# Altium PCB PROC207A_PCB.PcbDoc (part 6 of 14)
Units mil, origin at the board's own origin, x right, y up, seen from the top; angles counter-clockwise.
Board outline 4094.49 x 3724.79 mil, 8 copper layers (Top Layer, L2_GND1, L3_SIG1, L4_PWR1, L5_PWR2, L6_SIG2, L7_GND2, Bottom Layer), stack 58.1 mil thick; 584 components, 399 nets, 8440 pads, 5258 vias.
Unrouted connection lines stored in the file: 9.
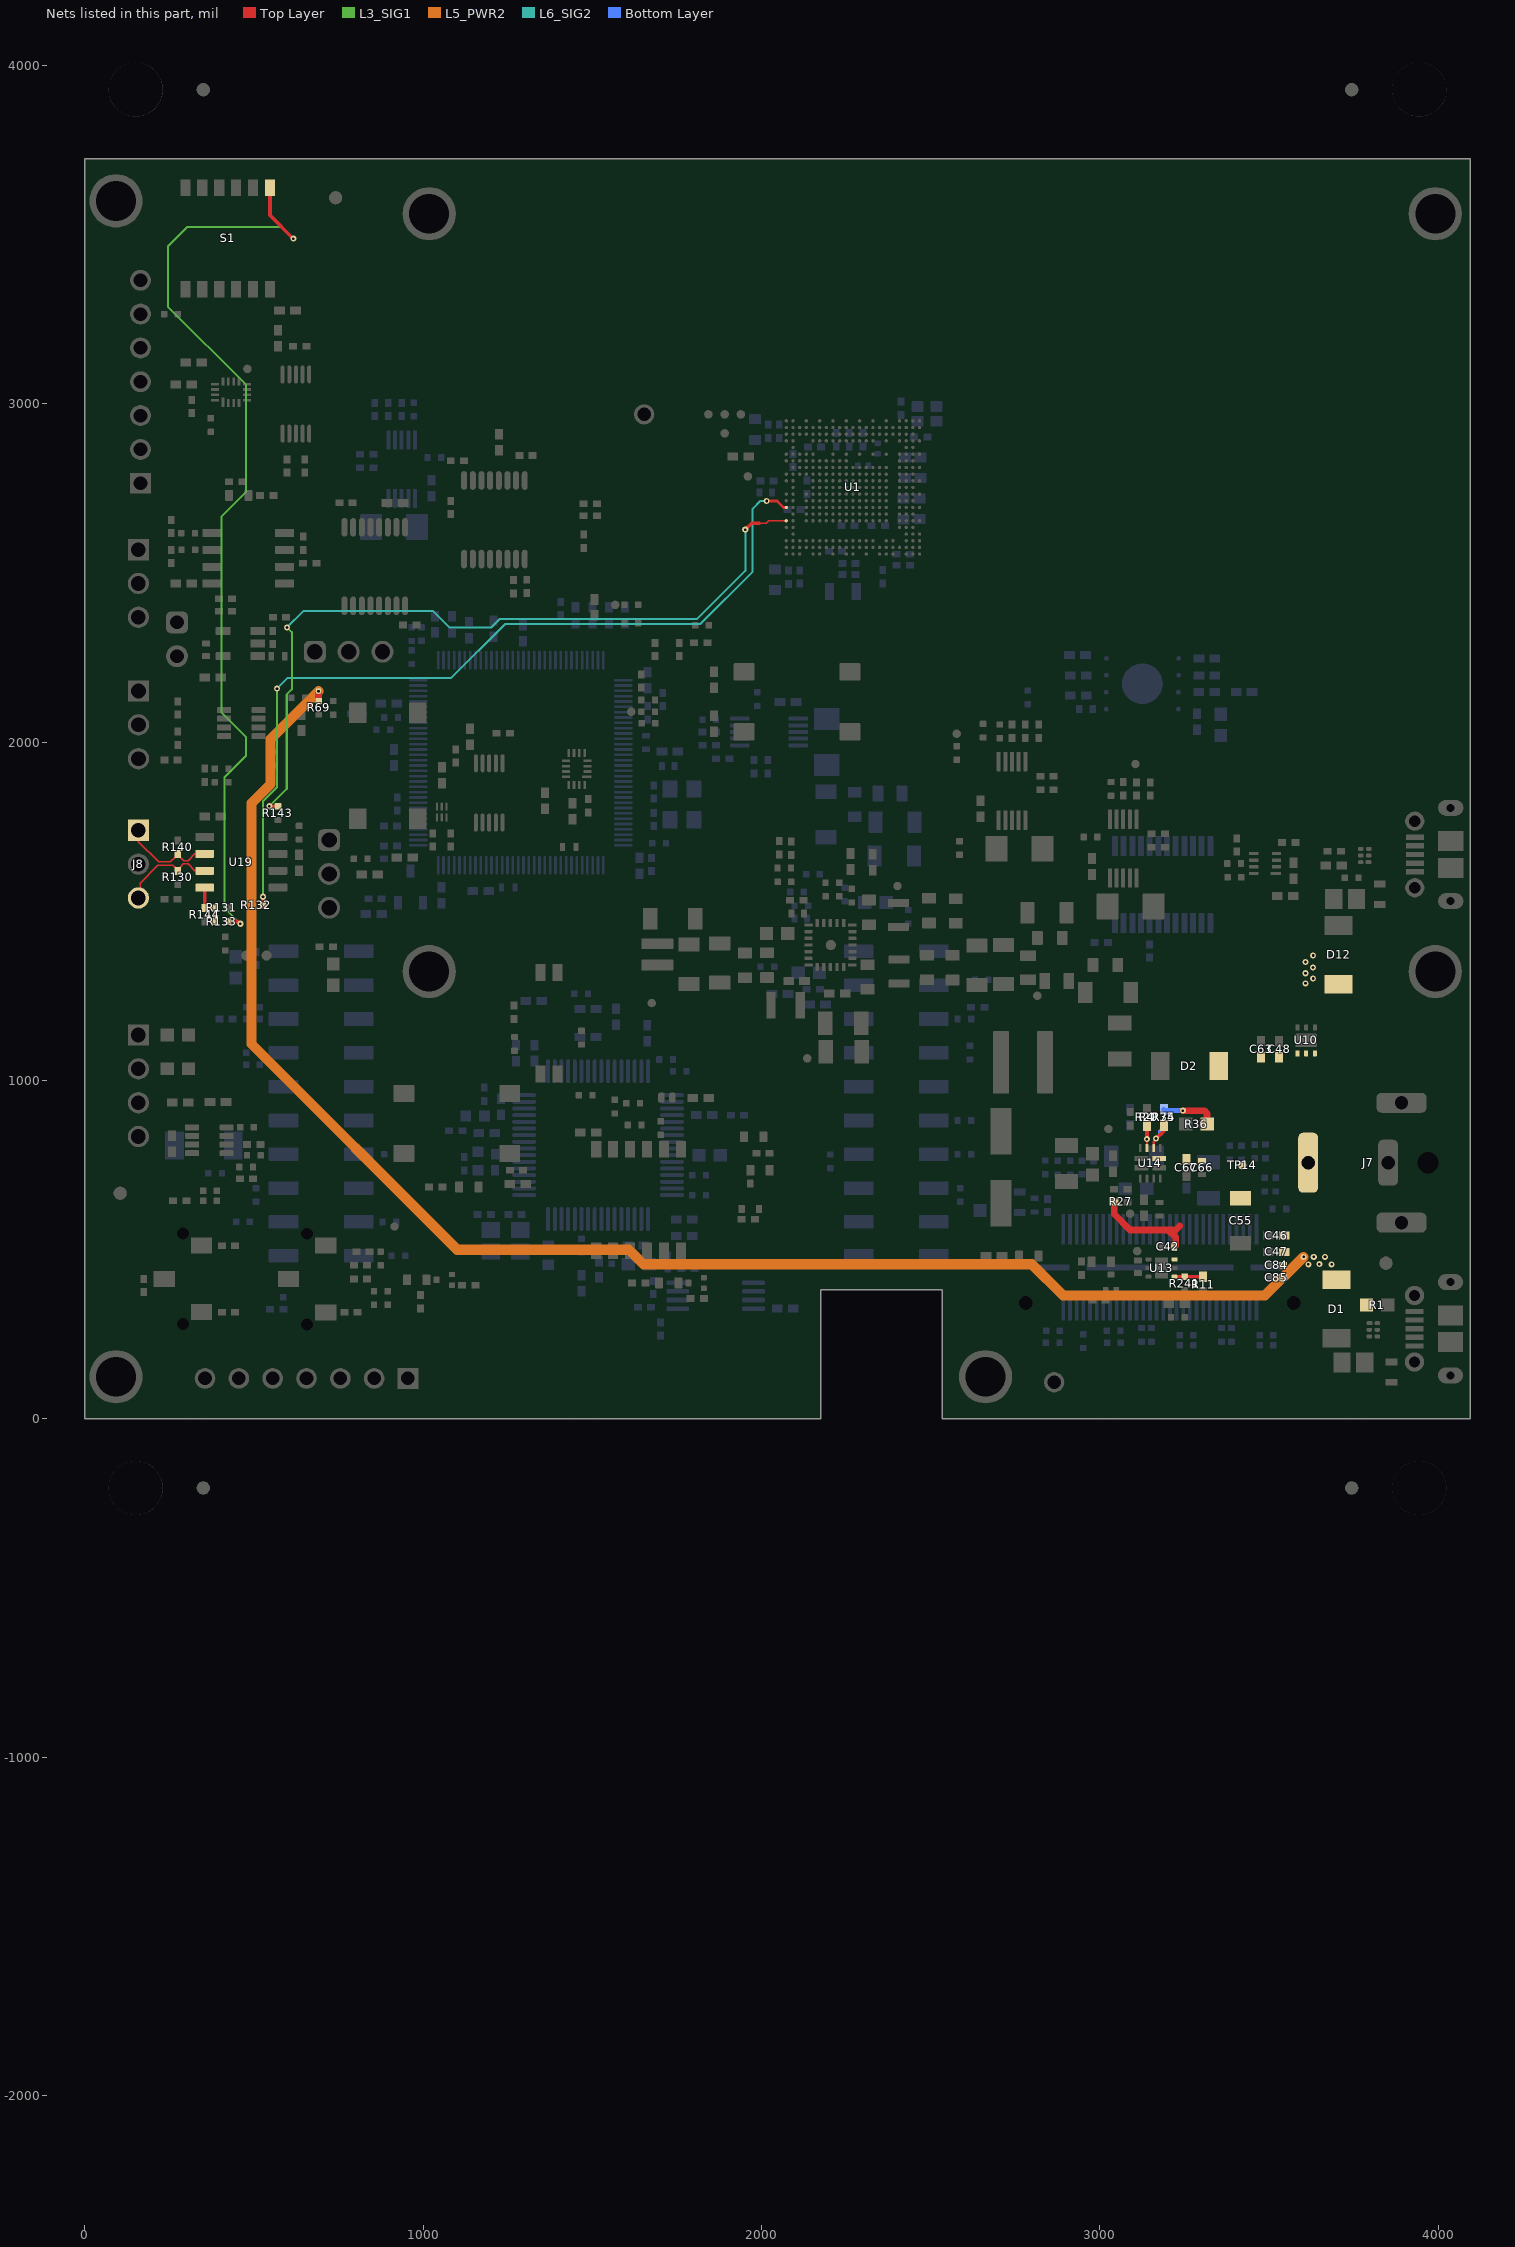
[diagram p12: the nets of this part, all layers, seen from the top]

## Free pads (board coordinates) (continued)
  round 5 on Mech16: 1(1064.44,825) 1(1064.44,825) 1(1064.44,876) 1(1064.44,876) 1(1075.69,801) 1(1075.69,801) 1(1075.69,809.15) 1(1075.69,809.15) 1(1075.69,811.43) 1(1075.69,811.43) 1(1075.69,818.93) 1(1075.69,818.93) 1(1075.69,825) 1(1075.69,825) 1(1084.72,528.51) 1(1084.72,528.51) 1(1084.72,528.53) 1(1084.72,528.53) 1(1084.72,585.53) 1(1084.72,585.53) 1(1084.72,585.55) 1(1084.72,585.55) 1(1087.72,525.53) 1(1087.72,525.53) 1(1087.72,588.53) 1(1087.72,588.53) 1(1093.19,801) 1(1093.19,801) 1(1093.19,809.15) 1(1093.19,809.15) 1(1093.19,811.43) 1(1093.19,811.43) 1(1093.19,818.93) 1(1093.19,818.93) 1(1093.19,825) 1(1093.19,825) 1(1097.34,501.03) 1(1097.34,501.03) 1(1097.34,509.58) 1(1097.34,509.58) 1(1097.34,513.22) 1(1097.34,513.22) 1(1097.34,514.48) 1(1097.34,514.48) 1(1097.34,524.44) 1(1097.34,524.44) 1(1097.34,525.53) 1(1097.34,525.53) 1(1097.34,588.53) 1(1097.34,588.53) 1(1097.34,589.61) 1(1097.34,589.61) 1(1097.34,599.58) 1(1097.34,599.58) 1(1097.34,600.84) 1(1097.34,600.84) 1(1097.34,604.48) 1(1097.34,604.48) 1(1097.34,613.03) 1(1097.34,613.03) 1(1112.1,501.03) 1(1112.1,501.03) 1(1112.1,509.58) 1(1112.1,509.58) 1(1112.1,513.22) 1(1112.1,513.22) 1(1112.1,514.48) 1(1112.1,514.48) 1(1112.1,524.44) 1(1112.1,524.44) 1(1112.1,525.53) 1(1112.1,525.53) 1(1112.1,588.53) 1(1112.1,588.53) 1(1112.1,589.61) 1(1112.1,589.61) 1(1112.1,599.58) 1(1112.1,599.58) 1(1112.1,600.84) 1(1112.1,600.84) 1(1112.1,604.48) 1(1112.1,604.48) 1(1112.1,613.03) 1(1112.1,613.03) 1(1113.19,876) 1(1113.19,876) 1(1113.19,882.06) 1(1113.19,882.06) 1(1113.19,889.56) 1(1113.19,889.56) 1(1113.19,891.84) 1(1113.19,891.84) 1(1113.19,900) 1(1113.19,900) 1(1130.69,876) 1(1130.69,876) 1(1130.69,882.06) 1(1130.69,882.06) 1(1130.69,889.56) 1(1130.69,889.56) 1(1130.69,891.84) 1(1130.69,891.84) 1(1130.69,900) 1(1130.69,900) 1(1134.84,501.03) 1(1134.84,501.03) 1(1134.84,509.58) 1(1134.84,509.58) 1(1134.84,513.22) 1(1134.84,513.22) 1(1134.84,514.48) 1(1134.84,514.48) 1(1134.84,524.44) 1(1134.84,524.44) 1(1134.84,525.53) 1(1134.84,525.53) 1(1134.84,588.53) 1(1134.84,588.53) 1(1134.84,589.61) 1(1134.84,589.61) 1(1134.84,599.58) 1(1134.84,599.58) 1(1134.84,600.84) 1(1134.84,600.84) 1(1134.84,604.48) 1(1134.84,604.48) 1(1134.84,613.03) 1(1134.84,613.03) 1(1149.6,501.03) 1(1149.6,501.03) 1(1149.6,509.58) 1(1149.6,509.58) 1(1149.6,513.22) 1(1149.6,513.22) 1(1149.6,514.48) 1(1149.6,514.48) 1(1149.6,524.44) 1(1149.6,524.44) 1(1149.6,525.53) 1(1149.6,525.53) 1(1149.6,588.53) 1(1149.6,588.53) 1(1149.6,589.61) 1(1149.6,589.61) 1(1149.6,599.58) 1(1149.6,599.58) 1(1149.6,600.84) 1(1149.6,600.84) 1(1149.6,604.48) 1(1149.6,604.48) 1(1149.6,613.03) 1(1149.6,613.03) 1(1150.69,801) 1(1150.69,801) 1(1150.69,809.15) 1(1150.69,809.15) 1(1150.69,811.43) 1(1150.69,811.43) 1(1150.69,818.93) 1(1150.69,818.93) 1(1150.69,825) 1(1150.69,825) 1(1168.19,801) 1(1168.19,801) 1(1168.19,809.15) 1(1168.19,809.15) 1(1168.19,811.43) 1(1168.19,811.43) 1(1168.19,818.93) 1(1168.19,818.93) 1(1168.19,825) 1(1168.19,825) 1(1172.34,501.03) 1(1172.34,501.03) 1(1172.34,509.58) 1(1172.34,509.58) 1(1172.34,513.22) 1(1172.34,513.22) 1(1172.34,514.48) 1(1172.34,514.48) 1(1172.34,524.44) 1(1172.34,524.44) 1(1172.34,525.53) 1(1172.34,525.53) 1(1172.34,588.53) 1(1172.34,588.53) 1(1172.34,589.61) 1(1172.34,589.61) 1(1172.34,599.58) 1(1172.34,599.58) 1(1172.34,600.84) 1(1172.34,600.84) 1(1172.34,604.48) 1(1172.34,604.48) 1(1172.34,613.03) 1(1172.34,613.03) 1(1178.47,534.35) 1(1178.47,534.35) 1(1178.47,544.35) 1(1178.47,544.35) 1(1179.44,825) 1(1179.44,825) 1(1179.44,876) 1(1179.44,876) 1(1187.1,501.03) 1(1187.1,501.03) 1(1187.1,509.58) 1(1187.1,509.58) 1(1187.1,513.22) 1(1187.1,513.22) 1(1187.1,514.48) 1(1187.1,514.48) 1(1187.1,524.44) 1(1187.1,524.44) 1(1187.1,525.53) 1(1187.1,525.53) 1(1187.1,588.53) 1(1187.1,588.53) 1(1187.1,589.61) 1(1187.1,589.61) 1(1187.1,599.58) 1(1187.1,599.58) 1(1187.1,600.84) 1(1187.1,600.84) 1(1187.1,604.48) 1(1187.1,604.48) 1(1187.1,613.03) 1(1187.1,613.03) 1(1196.73,525.53) 1(1196.73,525.53) 1(1196.73,588.53) 1(1196.73,588.53) 1(1199.72,528.51) 1(1199.72,528.51) 1(1199.72,528.53) 1(1199.72,528.53) 1(1199.72,585.53) 1(1199.72,585.53) 1(1199.72,585.55) 1(1199.72,585.55) 1(1305.8,-2261) 1(1305.8,-2261) 1(1305.8,-1761) 1(1305.8,-1761) 1(1896.1,465.3) 1(1896.1,465.3) 1(1896.1,475.15) 1(1896.1,475.15) 1(1896.1,490.89) 1(1896.1,490.89) 1(1896.1,500.74) 1(1896.1,500.74) 1(1896.1,516.48) 1(1896.1,516.48) 1(1896.1,526.33) 1(1896.1,526.33) 1(1896.1,542.07) 1(1896.1,542.07) 1(1896.1,551.92) 1(1896.1,551.92) 1(1907.91,465.3) 1(1907.91,465.3) 1(1907.91,475.15) 1(1907.91,475.15) 1(1907.91,490.89) 1(1907.91,490.89) 1(1907.91,500.74) 1(1907.91,500.74) 1(1907.91,516.48) 1(1907.91,516.48) 1(1907.91,526.33) 1(1907.91,526.33) 1(1907.91,542.07) 1(1907.91,542.07) 1(1907.91,551.92) 1(1907.91,551.92) 1(1913.33,465.3) 1(1913.33,465.3) 1(1913.33,475.15) 1(1913.33,475.15) 1(1913.33,490.89) 1(1913.33,490.89) 1(1913.33,500.74) 1(1913.33,500.74) 1(1913.33,516.48) 1(1913.33,516.48) 1(1913.33,526.33) 1(1913.33,526.33) 1(1913.33,542.07) 1(1913.33,542.07) 1(1913.33,551.92) 1(1913.33,551.92) 1(1918.55,465.3) 1(1918.55,465.3) 1(1918.55,475.15) 1(1918.55,475.15) 1(1918.55,490.89) 1(1918.55,490.89) 1(1918.55,500.74) 1(1918.55,500.74) 1(1918.55,516.48) 1(1918.55,516.48) 1(1918.55,526.33) 1(1918.55,526.33) 1(1918.55,542.07) 1(1918.55,542.07) 1(1918.55,551.92) 1(1918.55,551.92) 1(1927.59,465.3) 1(1927.59,465.3) 1(1927.59,475.15) 1(1927.59,475.15) 1(1927.59,490.89) 1(1927.59,490.89) 1(1927.59,500.74) 1(1927.59,500.74) 1(1927.59,516.48) 1(1927.59,516.48) 1(1927.59,526.33) 1(1927.59,526.33) 1(1927.59,542.07) 1(1927.59,542.07) 1(1927.59,551.92) 1(1927.59,551.92) 1(1933.5,447.39) 1(1933.5,447.39) 1(1933.5,447.39) 1(1933.5,465.3) 1(1933.5,465.3) 1(1933.5,475.15) 1(1933.5,475.15) 1(1933.5,490.89) 1(1933.5,490.89) 1(1933.5,500.74) 1(1933.5,500.74) 1(1933.5,516.48) 1(1933.5,516.48) 1(1933.5,526.33) 1(1933.5,526.33) 1(1933.5,542.07) 1(1933.5,542.07) 1(1933.5,551.92) 1(1933.5,551.92) 1(1933.5,569.44) 1(1933.5,569.44) 1(1933.5,569.44) 1(1937.26,451.16) 1(1937.26,451.16) 1(1937.26,451.16) 1(1937.26,565.67) 1(1937.26,565.67) 1(1937.26,565.67) 1(1952.05,316.38) 1(1952.05,316.38) 1(1952.05,327.06) 1(1952.05,327.06) 1(1952.05,336.06) 1(1952.05,336.06) 1(1952.05,346.74) 1(1952.05,346.74) 1(1952.05,375.42) 1(1952.05,375.42) 1(1952.05,386.1) 1(1952.05,386.1) 1(1952.05,307.38) 1(1952.05,307.38) 1(1952.05,355.74) 1(1952.05,355.74) 1(1952.05,366.42) 1(1952.05,366.42) 1(1952.05,395.1) 1(1952.05,395.1) 1(1953.18,459.2) 1(1953.18,459.2) 1(1953.18,474.95) 1(1953.18,474.95) 1(1961.49,307.38) 1(1961.49,307.38) 1(1961.49,316.38) 1(1961.49,316.38) 1(1961.49,327.06) 1(1961.49,327.06) 1(1961.49,336.06) 1(1961.49,336.06) 1(1961.49,346.74) 1(1961.49,346.74) 1(1961.49,355.74) 1(1961.49,355.74) 1(1961.49,366.42) 1(1961.49,366.42) 1(1961.49,375.42) 1(1961.49,375.42) 1(1961.49,386.1) 1(1961.49,386.1) 1(1961.49,395.1) 1(1961.49,395.1) 1(1966.21,307.38) 1(1966.21,307.38) 1(1966.21,316.38) 1(1966.21,316.38) 1(1966.21,327.06) 1(1966.21,327.06) 1(1966.21,336.06) 1(1966.21,336.06) 1(1966.21,346.74) 1(1966.21,346.74) 1(1966.21,355.74) 1(1966.21,355.74) 1(1966.21,366.42) 1(1966.21,366.42) 1(1966.21,375.42) 1(1966.21,375.42) 1(1966.21,386.1) 1(1966.21,386.1) 1(1966.21,395.1) 1(1966.21,395.1) 1(1966.34,307.38) 1(1966.34,307.38) 1(1966.34,316.38) 1(1966.34,316.38) 1(1966.34,327.06) 1(1966.34,327.06) 1(1966.34,336.06) 1(1966.34,336.06) 1(1966.34,346.74) 1(1966.34,346.74) 1(1966.34,355.74) 1(1966.34,355.74) 1(1966.34,366.42) 1(1966.34,366.42) 1(1966.34,375.42) 1(1966.34,375.42) 1(1966.34,386.1) 1(1966.34,386.1) 1(1966.34,395.1) 1(1966.34,395.1) 1(1978.29,307.38) 1(1978.29,307.38) 1(1978.29,316.38) 1(1978.29,316.38) 1(1978.29,327.06) 1(1978.29,327.06) 1(1978.29,336.06) 1(1978.29,336.06) 1(1978.29,346.74) 1(1978.29,346.74) 1(1978.29,355.74) 1(1978.29,355.74) 1(1978.29,366.42) 1(1978.29,366.42) 1(1978.29,375.42) 1(1978.29,375.42) 1(1978.29,386.1) 1(1978.29,386.1) 1(1978.29,395.1) 1(1978.29,395.1) 1(1989.55,297.24) 1(1989.55,297.24) 1(1989.55,307.38) 1(1989.55,307.38) 1(1989.55,316.38) 1(1989.55,316.38) 1(1989.55,327.06) 1(1989.55,327.06) 1(1989.55,336.06) 1(1989.55,336.06) 1(1989.55,346.74) 1(1989.55,346.74) 1(1989.55,355.74) 1(1989.55,355.74) 1(1989.55,366.42) 1(1989.55,366.42) 1(1989.55,375.42) 1(1989.55,375.42) 1(1989.55,386.1) 1(1989.55,386.1) 1(1989.55,395.1) 1(1989.55,395.1) 1(1989.55,405.24) 1(1989.55,405.24) 1(1989.56,297.14) 1(1989.56,297.14) 1(1989.56,405.35) 1(1989.56,405.35) 1(1990.64,-469.68) 1(1990.64,-469.68) 1(1990.64,-389.68) 1(1990.64,-389.68) 1(1990.64,-73.54) 1(1990.64,-73.54) 1(1990.64,6.46) 1(1990.64,6.46) 1(1994.45,292.24) 1(1994.45,292.24) 1(1994.45,410.24) 1(1994.45,410.24) 1(1994.55,292.24) 1(1994.55,292.24) 1(1994.55,410.24) 1(1994.55,410.24) 1(1996.55,313.24) 1(1996.55,313.24) 1(2010.36,-819.84) 1(2010.36,-819.84) 1(2010.36,-809.16) 1(2010.36,-809.16) 1(2010.36,-800.16) 1(2010.36,-800.16) 1(2010.36,-789.48) 1(2010.36,-789.48) 1(2010.36,-760.8) 1(2010.36,-760.8) 1(2010.36,-750.12) 1(2010.36,-750.12) 1(2010.36,-828.84) 1(2010.36,-828.84) 1(2010.36,-780.48) 1(2010.36,-780.48) 1(2010.36,-769.8) 1(2010.36,-769.8) 1(2010.36,-741.12) 1(2010.36,-741.12) 1(2019.79,-828.84) 1(2019.79,-828.84) 1(2019.79,-819.84) 1(2019.79,-819.84) 1(2019.79,-809.16) 1(2019.79,-809.16) 1(2019.79,-800.16) 1(2019.79,-800.16) 1(2019.79,-789.48) 1(2019.79,-789.48) 1(2019.79,-780.48) 1(2019.79,-780.48) 1(2019.79,-769.8) 1(2019.79,-769.8) 1(2019.79,-760.8) 1(2019.79,-760.8) 1(2019.79,-750.12) 1(2019.79,-750.12) 1(2019.79,-741.12) 1(2019.79,-741.12) 1(2024.51,-828.84) 1(2024.51,-828.84) 1(2024.51,-819.84) 1(2024.51,-819.84) 1(2024.51,-809.16) 1(2024.51,-809.16) 1(2024.51,-800.16) 1(2024.51,-800.16) 1(2024.51,-789.48) 1(2024.51,-789.48) 1(2024.51,-780.48) 1(2024.51,-780.48) 1(2024.51,-769.8) 1(2024.51,-769.8) 1(2024.51,-760.8) 1(2024.51,-760.8) 1(2024.51,-750.12) 1(2024.51,-750.12) 1(2024.51,-741.12) 1(2024.51,-741.12) 1(2024.55,313.24) 1(2024.55,313.24) 1(2024.64,-828.84) 1(2024.64,-828.84) 1(2024.64,-819.84) 1(2024.64,-819.84) 1(2024.64,-809.16) 1(2024.64,-809.16) 1(2024.64,-800.16) 1(2024.64,-800.16) 1(2024.64,-789.48) 1(2024.64,-789.48) 1(2024.64,-780.48) 1(2024.64,-780.48) 1(2024.64,-769.8) 1(2024.64,-769.8) 1(2024.64,-760.8) 1(2024.64,-760.8) 1(2024.64,-750.12) 1(2024.64,-750.12) 1(2024.64,-741.12) 1(2024.64,-741.12) 1(2036.6,-828.84) 1(2036.6,-828.84) 1(2036.6,-819.84) 1(2036.6,-819.84) 1(2036.6,-809.16) 1(2036.6,-809.16) 1(2036.6,-800.16) 1(2036.6,-800.16) 1(2036.6,-789.48) 1(2036.6,-789.48) 1(2036.6,-780.48) 1(2036.6,-780.48) 1(2036.6,-769.8) 1(2036.6,-769.8) 1(2036.6,-760.8) 1(2036.6,-760.8) 1(2036.6,-750.12) 1(2036.6,-750.12) 1(2036.6,-741.12) 1(2036.6,-741.12) 1(2047.86,-838.98) 1(2047.86,-838.98) 1(2047.86,-828.84) 1(2047.86,-828.84) 1(2047.86,-819.84) 1(2047.86,-819.84) 1(2047.86,-809.16) 1(2047.86,-809.16) 1(2047.86,-800.16) 1(2047.86,-800.16) 1(2047.86,-789.48) 1(2047.86,-789.48) 1(2047.86,-780.48) 1(2047.86,-780.48) 1(2047.86,-769.8) 1(2047.86,-769.8) 1(2047.86,-760.8) 1(2047.86,-760.8) 1(2047.86,-750.12) 1(2047.86,-750.12) 1(2047.86,-741.12) 1(2047.86,-741.12) 1(2047.86,-730.98) 1(2047.86,-730.98) 1(2047.86,-839.09) 1(2047.86,-839.09) 1(2047.86,-730.87) 1(2047.86,-730.87) 1(2052.75,-843.98) 1(2052.75,-843.98) 1(2052.75,-725.98) 1(2052.75,-725.98) 1(2052.86,-843.98) 1(2052.86,-843.98) 1(2052.86,-725.98) 1(2052.86,-725.98) 1(2054.86,-822.98) 1(2054.86,-822.98) 1(2082.86,-822.98) 1(2082.86,-822.98) 1(2102.55,292.24) 1(2102.55,292.24) 1(2102.55,410.24) 1(2102.55,410.24) 1(2102.66,292.24) 1(2102.66,292.24) 1(2102.66,410.24) 1(2102.66,410.24) 1(2106.9,451.16) 1(2106.9,451.16) 1(2106.9,451.16) 1(2106.9,565.67) 1(2106.9,565.67) 1(2106.9,565.67) 1(2107.55,297.14) 1(2107.55,297.14) 1(2107.55,405.35) 1(2107.55,405.35) 1(2107.55,297.24) 1(2107.55,297.24) 1(2107.55,307.38) 1(2107.55,307.38) 1(2107.55,316.38) 1(2107.55,316.38) 1(2107.55,327.06) 1(2107.55,327.06) 1(2107.55,336.06) 1(2107.55,336.06) 1(2107.55,346.74) 1(2107.55,346.74) 1(2107.55,355.74) 1(2107.55,355.74) 1(2107.55,366.42) 1(2107.55,366.42) 1(2107.55,375.42) 1(2107.55,375.42) 1(2107.55,386.1) 1(2107.55,386.1) 1(2107.55,395.1) 1(2107.55,395.1) 1(2107.55,405.24) 1(2107.55,405.24) 1(2110.66,447.39) 1(2110.66,447.39) 1(2110.66,447.39) 1(2110.66,465.3) 1(2110.66,465.3) 1(2110.66,475.15) 1(2110.66,475.15) 1(2110.66,490.89) 1(2110.66,490.89) 1(2110.66,500.74) 1(2110.66,500.74) 1(2110.66,516.48) 1(2110.66,516.48) 1(2110.66,526.33) 1(2110.66,526.33) 1(2110.66,542.07) 1(2110.66,542.07) 1(2110.66,551.92) 1(2110.66,551.92) 1(2110.66,569.44) 1(2110.66,569.44) 1(2110.66,569.44) 1(2116.57,465.3) 1(2116.57,465.3) 1(2116.57,475.15) 1(2116.57,475.15) 1(2116.57,490.89) 1(2116.57,490.89) 1(2116.57,500.74) 1(2116.57,500.74) 1(2116.57,516.48) 1(2116.57,516.48) 1(2116.57,526.33) 1(2116.57,526.33) 1(2116.57,542.07) 1(2116.57,542.07) 1(2116.57,551.92) 1(2116.57,551.92) 1(2118.82,307.38) 1(2118.82,307.38) 1(2118.82,316.38) 1(2118.82,316.38) 1(2118.82,327.06) 1(2118.82,327.06) 1(2118.82,336.06) 1(2118.82,336.06) 1(2118.82,346.74) 1(2118.82,346.74) 1(2118.82,355.74) 1(2118.82,355.74) 1(2118.82,366.42) 1(2118.82,366.42) 1(2118.82,395.1) 1(2118.82,395.1) 1(2118.82,375.42) 1(2118.82,375.42) 1(2118.82,386.1) 1(2118.82,386.1) 1(2125.61,465.3) 1(2125.61,465.3) 1(2125.61,475.15) 1(2125.61,475.15) 1(2125.61,490.89) 1(2125.61,490.89) 1(2125.61,500.74) 1(2125.61,500.74) 1(2125.61,516.48) 1(2125.61,516.48) 1(2125.61,526.33) 1(2125.61,526.33) 1(2125.61,542.07) 1(2125.61,542.07) 1(2125.61,551.92) 1(2125.61,551.92) 1(2130.77,307.38) 1(2130.77,307.38) 1(2130.77,316.38) 1(2130.77,316.38) 1(2130.77,327.06) 1(2130.77,327.06) 1(2130.77,336.06) 1(2130.77,336.06) 1(2130.77,346.74) 1(2130.77,346.74) 1(2130.77,355.74) 1(2130.77,355.74) 1(2130.77,366.42) 1(2130.77,366.42) 1(2130.77,375.42) 1(2130.77,375.42) 1(2130.77,386.1) 1(2130.77,386.1) 1(2130.77,395.1) 1(2130.77,395.1) 1(2130.83,465.3) 1(2130.83,465.3) 1(2130.83,475.15) 1(2130.83,475.15) 1(2130.83,490.89) 1(2130.83,490.89) 1(2130.83,500.74) 1(2130.83,500.74) 1(2130.83,516.48) 1(2130.83,516.48) 1(2130.83,526.33) 1(2130.83,526.33) 1(2130.83,542.07) 1(2130.83,542.07) 1(2130.83,551.92) 1(2130.83,551.92) 1(2130.9,375.42) 1(2130.9,375.42) 1(2130.9,386.1) 1(2130.9,386.1) 1(2130.9,307.38) 1(2130.9,307.38) 1(2130.9,316.38) 1(2130.9,316.38) 1(2130.9,327.06) 1(2130.9,327.06) 1(2130.9,336.06) 1(2130.9,336.06) 1(2130.9,346.74) 1(2130.9,346.74) 1(2130.9,355.74) 1(2130.9,355.74) 1(2130.9,366.42) 1(2130.9,366.42) 1(2130.9,395.1) 1(2130.9,395.1) 1(2135.62,307.38) 1(2135.62,307.38) 1(2135.62,316.38) 1(2135.62,316.38) 1(2135.62,327.06) 1(2135.62,327.06) 1(2135.62,336.06) 1(2135.62,336.06) 1(2135.62,346.74) 1(2135.62,346.74) 1(2135.62,355.74) 1(2135.62,355.74) 1(2135.62,366.42) 1(2135.62,366.42) 1(2135.62,375.42) 1(2135.62,375.42) 1(2135.62,386.1) 1(2135.62,386.1) 1(2135.62,395.1) 1(2135.62,395.1) 1(2136.25,465.3) 1(2136.25,465.3) 1(2136.25,475.15) 1(2136.25,475.15) 1(2136.25,490.89) 1(2136.25,490.89) 1(2136.25,500.74) 1(2136.25,500.74) 1(2136.25,516.48) 1(2136.25,516.48) 1(2136.25,526.33) 1(2136.25,526.33) 1(2136.25,542.07) 1(2136.25,542.07) 1(2136.25,551.92) 1(2136.25,551.92) 1(2136.64,-73.54) 1(2136.64,-73.54) 1(2136.64,6.46) 1(2136.64,6.46) 1(2138.64,-469.68) 1(2138.64,-469.68) 1(2138.64,-469.54) 1(2138.64,-469.54) 1(2138.64,-389.68) 1(2138.64,-389.68) 1(2138.64,-389.54) 1(2138.64,-389.54) 1(2138.64,-73.54) 1(2138.64,-73.54) 1(2138.64,6.46) 1(2138.64,6.46) 1(2145.05,307.38) 1(2145.05,307.38) 1(2145.05,316.38) 1(2145.05,316.38) 1(2145.05,327.06) 1(2145.05,327.06) 1(2145.05,336.06) 1(2145.05,336.06) 1(2145.05,346.74) 1(2145.05,346.74) 1(2145.05,355.74) 1(2145.05,355.74) 1(2145.05,366.42) 1(2145.05,366.42) 1(2145.05,375.42) 1(2145.05,375.42) 1(2145.05,386.1) 1(2145.05,386.1) 1(2145.05,395.1) 1(2145.05,395.1) 1(2148.06,465.3) 1(2148.06,465.3) 1(2148.06,475.15) 1(2148.06,475.15) 1(2148.06,490.89) 1(2148.06,490.89) 1(2148.06,500.74) 1(2148.06,500.74) 1(2148.06,516.48) 1(2148.06,516.48) 1(2148.06,526.33) 1(2148.06,526.33) 1(2148.06,542.07) 1(2148.06,542.07) 1(2148.06,551.92) 1(2148.06,551.92) 1(2160.86,-843.98) 1(2160.86,-843.98) 1(2160.86,-725.98) 1(2160.86,-725.98) 1(2160.97,-843.98) 1(2160.97,-843.98) 1(2160.97,-725.98) 1(2160.97,-725.98) 1(2165.86,-839.09) 1(2165.86,-839.09) 1(2165.86,-730.87) 1(2165.86,-730.87) 1(2165.86,-838.98) 1(2165.86,-838.98) 1(2165.86,-828.84) 1(2165.86,-828.84) 1(2165.86,-819.84) 1(2165.86,-819.84) 1(2165.86,-809.16) 1(2165.86,-809.16) 1(2165.86,-800.16) 1(2165.86,-800.16) 1(2165.86,-789.48) 1(2165.86,-789.48) 1(2165.86,-780.48) 1(2165.86,-780.48) 1(2165.86,-769.8) 1(2165.86,-769.8) 1(2165.86,-760.8) 1(2165.86,-760.8) 1(2165.86,-750.12) 1(2165.86,-750.12) 1(2165.86,-741.12) 1(2165.86,-741.12) 1(2165.86,-730.98) 1(2165.86,-730.98) 1(2177.12,-828.84) 1(2177.12,-828.84) 1(2177.12,-819.84) 1(2177.12,-819.84) 1(2177.12,-809.16) 1(2177.12,-809.16) 1(2177.12,-800.16) 1(2177.12,-800.16) 1(2177.12,-789.48) 1(2177.12,-789.48) 1(2177.12,-780.48) 1(2177.12,-780.48) 1(2177.12,-769.8) 1(2177.12,-769.8) 1(2177.12,-741.12) 1(2177.12,-741.12) 1(2177.12,-760.8) 1(2177.12,-760.8) 1(2177.12,-750.12) 1(2177.12,-750.12) 1(2189.08,-828.84) 1(2189.08,-828.84) 1(2189.08,-819.84) 1(2189.08,-819.84) 1(2189.08,-809.16) 1(2189.08,-809.16) 1(2189.08,-800.16) 1(2189.08,-800.16) 1(2189.08,-789.48) 1(2189.08,-789.48) 1(2189.08,-780.48) 1(2189.08,-780.48) 1(2189.08,-769.8) 1(2189.08,-769.8) 1(2189.08,-760.8) 1(2189.08,-760.8) 1(2189.08,-750.12) 1(2189.08,-750.12) 1(2189.08,-741.12) 1(2189.08,-741.12) 1(2189.21,-760.8) 1(2189.21,-760.8) 1(2189.21,-750.12) 1(2189.21,-750.12) 1(2189.21,-828.84) 1(2189.21,-828.84) 1(2189.21,-819.84) 1(2189.21,-819.84) 1(2189.21,-809.16) 1(2189.21,-809.16) 1(2189.21,-800.16) 1(2189.21,-800.16) 1(2189.21,-789.48) 1(2189.21,-789.48) 1(2189.21,-780.48) 1(2189.21,-780.48) 1(2189.21,-769.8) 1(2189.21,-769.8) 1(2189.21,-741.12) 1(2189.21,-741.12) 1(2193.93,-828.84) 1(2193.93,-828.84) 1(2193.93,-819.84) 1(2193.93,-819.84) 1(2193.93,-809.16) 1(2193.93,-809.16) 1(2193.93,-800.16) 1(2193.93,-800.16) 1(2193.93,-789.48) 1(2193.93,-789.48) 1(2193.93,-780.48) 1(2193.93,-780.48) 1(2193.93,-769.8) 1(2193.93,-769.8) 1(2193.93,-760.8) 1(2193.93,-760.8) 1(2193.93,-750.12) 1(2193.93,-750.12) 1(2193.93,-741.12) 1(2193.93,-741.12) 1(2203.36,-828.84) 1(2203.36,-828.84) 1(2203.36,-819.84) 1(2203.36,-819.84) 1(2203.36,-809.16) 1(2203.36,-809.16) 1(2203.36,-800.16) 1(2203.36,-800.16) 1(2203.36,-789.48) 1(2203.36,-789.48) 1(2203.36,-780.48) 1(2203.36,-780.48) 1(2203.36,-769.8) 1(2203.36,-769.8) 1(2203.36,-760.8) 1(2203.36,-760.8) 1(2203.36,-750.12) 1(2203.36,-750.12) 1(2203.36,-741.12) 1(2203.36,-741.12) 1(2205.8,-2261) 1(2205.8,-2261) 1(2205.8,-1761) 1(2205.8,-1761) 1(2284.64,-73.54) 1(2284.64,-73.54) 1(2284.64,6.46) 1(2284.64,6.46) 1(2286.64,-469.54) 1(2286.64,-469.54) 1(2286.64,-389.54) 1(2286.64,-389.54) 1(2320.42,-2230.5) 1(2320.42,-2230.5) 1(2320.42,-2221.51) 1(2320.42,-2221.51) 1(2320.42,-2082.5) 1(2320.42,-2082.5) 1(2320.42,-2073.5) 1(2320.42,-2073.5) 1(2470.24,-613.36) 1(2470.24,-613.36) 1(2470.24,-604.36) 1(2470.24,-604.36) 1(2470.24,-593.68) 1(2470.24,-593.68) 1(2470.24,-584.68) 1(2470.24,-584.68) 1(2470.24,-574) 1(2470.24,-574) 1(2470.24,-565) 1(2470.24,-565) 1(2470.24,-554.32) 1(2470.24,-554.32) 1(2470.24,-545.32) 1(2470.24,-545.32) 1(2470.24,-534.64) 1(2470.24,-534.64) 1(2470.24,-525.64) 1(2470.24,-525.64) 1(2479.68,-613.36) 1(2479.68,-613.36) 1(2479.68,-604.36) 1(2479.68,-604.36) 1(2479.68,-593.68) 1(2479.68,-593.68) 1(2479.68,-584.68) 1(2479.68,-584.68) 1(2479.68,-574) 1(2479.68,-574) 1(2479.68,-565) 1(2479.68,-565) 1(2479.68,-554.32) 1(2479.68,-554.32) 1(2479.68,-545.32) 1(2479.68,-545.32) 1(2479.68,-534.64) 1(2479.68,-534.64) 1(2479.68,-525.64) 1(2479.68,-525.64) 1(2484.4,-613.36) 1(2484.4,-613.36) 1(2484.4,-604.36) 1(2484.4,-604.36) 1(2484.4,-593.68) 1(2484.4,-593.68) 1(2484.4,-584.68) 1(2484.4,-584.68) 1(2484.4,-574) 1(2484.4,-574) 1(2484.4,-565) 1(2484.4,-565) 1(2484.4,-554.32) 1(2484.4,-554.32) 1(2484.4,-545.32) 1(2484.4,-545.32) 1(2484.4,-534.64) 1(2484.4,-534.64) 1(2484.4,-525.64) 1(2484.4,-525.64) 1(2484.53,-613.36) 1(2484.53,-613.36) 1(2484.53,-604.36) 1(2484.53,-604.36) 1(2484.53,-593.68) 1(2484.53,-593.68) 1(2484.53,-584.68) 1(2484.53,-584.68) 1(2484.53,-574) 1(2484.53,-574) 1(2484.53,-565) 1(2484.53,-565) 1(2484.53,-554.32) 1(2484.53,-554.32) 1(2484.53,-545.32) 1(2484.53,-545.32) 1(2484.53,-534.64) 1(2484.53,-534.64) 1(2484.53,-525.64) 1(2484.53,-525.64) 1(2496.48,-613.36) 1(2496.48,-613.36) 1(2496.48,-604.36) 1(2496.48,-604.36) 1(2496.48,-593.68) 1(2496.48,-593.68) 1(2496.48,-584.68) 1(2496.48,-584.68) 1(2496.48,-574) 1(2496.48,-574) 1(2496.48,-565) 1(2496.48,-565) 1(2496.48,-554.32) 1(2496.48,-554.32) 1(2496.48,-545.32) 1(2496.48,-545.32) 1(2496.48,-534.64) 1(2496.48,-534.64) 1(2496.48,-525.64) 1(2496.48,-525.64) 1(2507.74,-623.5) 1(2507.74,-623.5) 1(2507.74,-613.36) 1(2507.74,-613.36) 1(2507.74,-604.36) 1(2507.74,-604.36) 1(2507.74,-593.68) 1(2507.74,-593.68) 1(2507.74,-584.68) 1(2507.74,-584.68) 1(2507.74,-574) 1(2507.74,-574) 1(2507.74,-565) 1(2507.74,-565) 1(2507.74,-554.32) 1(2507.74,-554.32) 1(2507.74,-545.32) 1(2507.74,-545.32) 1(2507.74,-534.64) 1(2507.74,-534.64) 1(2507.74,-525.64) 1(2507.74,-525.64) 1(2507.74,-515.5) 1(2507.74,-515.5) 1(2507.74,-623.61) 1(2507.74,-623.61) 1(2507.74,-515.39) 1(2507.74,-515.39) 1(2508.79,-2005.95) 1(2508.79,-2005.95) 1(2508.79,-1857.95) 1(2508.79,-1857.95) 1(2512.63,-628.5) 1(2512.63,-628.5) 1(2512.63,-510.5) 1(2512.63,-510.5) 1(2512.74,-628.5) 1(2512.74,-628.5) 1(2512.74,-510.5) 1(2512.74,-510.5) 1(2587.42,-2230.5) 1(2587.42,-2073.5) 1(2588.79,-2005.95) 1(2588.79,-2005.95) 1(2588.79,-1857.95) 1(2588.79,-1857.95) 1(2590.74,-531.5) 1(2590.74,-531.5) 1(2598.79,-2005.95) 1(2598.79,-2005.95) 1(2598.79,-1857.95) 1(2598.79,-1857.95) 1(2618.74,-531.5) 1(2618.74,-531.5) 1(2620.74,-628.5) 1(2620.74,-628.5) 1(2620.74,-510.5) 1(2620.74,-510.5) 1(2620.85,-628.5) 1(2620.85,-628.5) 1(2620.85,-510.5) 1(2620.85,-510.5) 1(2625.74,-623.61) 1(2625.74,-623.61) 1(2625.74,-515.39) 1(2625.74,-515.39) 1(2625.74,-623.5) 1(2625.74,-623.5) 1(2625.74,-613.36) 1(2625.74,-613.36) 1(2625.74,-604.36) 1(2625.74,-604.36) 1(2625.74,-593.68) 1(2625.74,-593.68) 1(2625.74,-584.68) 1(2625.74,-584.68) 1(2625.74,-574) 1(2625.74,-574) 1(2625.74,-565) 1(2625.74,-565) 1(2625.74,-554.32) 1(2625.74,-554.32) 1(2625.74,-545.32) 1(2625.74,-545.32) 1(2625.74,-534.64) 1(2625.74,-534.64) 1(2625.74,-525.64) 1(2625.74,-525.64) 1(2625.74,-515.5) 1(2625.74,-515.5) 1(2637,-613.36) 1(2637,-613.36) 1(2637,-604.36) 1(2637,-604.36) 1(2637,-593.68) 1(2637,-593.68) 1(2637,-584.68) 1(2637,-584.68) 1(2637,-574) 1(2637,-574) 1(2637,-565) 1(2637,-565) 1(2637,-554.32) 1(2637,-554.32) 1(2637,-545.32) 1(2637,-545.32) 1(2637,-534.64) 1(2637,-534.64) 1(2637,-525.64) 1(2637,-525.64) 1(2648.96,-613.36) 1(2648.96,-613.36) 1(2648.96,-604.36) 1(2648.96,-604.36) 1(2648.96,-593.68) 1(2648.96,-593.68) 1(2648.96,-584.68) 1(2648.96,-584.68) 1(2648.96,-574) 1(2648.96,-574) 1(2648.96,-565) 1(2648.96,-565) 1(2648.96,-554.32) 1(2648.96,-554.32) 1(2648.96,-545.32) 1(2648.96,-545.32) 1(2648.96,-534.64) 1(2648.96,-534.64) 1(2648.96,-525.64) 1(2648.96,-525.64) 1(2649.09,-613.36) 1(2649.09,-613.36) 1(2649.09,-604.36) 1(2649.09,-604.36) 1(2649.09,-593.68) 1(2649.09,-593.68) 1(2649.09,-584.68) 1(2649.09,-584.68) 1(2649.09,-574) 1(2649.09,-574) 1(2649.09,-565) 1(2649.09,-565) 1(2649.09,-554.32) 1(2649.09,-554.32) 1(2649.09,-545.32) 1(2649.09,-545.32) 1(2649.09,-534.64) 1(2649.09,-534.64) 1(2649.09,-525.64) 1(2649.09,-525.64) 1(2653.81,-613.36) 1(2653.81,-613.36) 1(2653.81,-604.36) 1(2653.81,-604.36) 1(2653.81,-593.68) 1(2653.81,-593.68) 1(2653.81,-584.68) 1(2653.81,-584.68) 1(2653.81,-574) 1(2653.81,-574) 1(2653.81,-565) 1(2653.81,-565) 1(2653.81,-554.32) 1(2653.81,-554.32) 1(2653.81,-545.32) 1(2653.81,-545.32) 1(2653.81,-534.64) 1(2653.81,-534.64) 1(2653.81,-525.64) 1(2653.81,-525.64) 1(2663.24,-613.36) 1(2663.24,-613.36) 1(2663.24,-604.36) 1(2663.24,-604.36) 1(2663.24,-593.68) 1(2663.24,-593.68) 1(2663.24,-584.68) 1(2663.24,-584.68) 1(2663.24,-574) 1(2663.24,-574) 1(2663.24,-565) 1(2663.24,-565) 1(2663.24,-554.32) 1(2663.24,-554.32) 1(2663.24,-545.32) 1(2663.24,-545.32) 1(2663.24,-534.64) 1(2663.24,-534.64) 1(2663.24,-525.64) 1(2663.24,-525.64) 1(2678.79,-2005.95) 1(2678.79,-2005.95) 1(2678.79,-1857.95) 1(2678.79,-1857.95) 1(2748.79,1802.05) 1(2748.79,1802.05) 1(2748.79,1950.05) 1(2748.79,1950.05) 1(2828.79,1802.05) 1(2828.79,1802.05) 1(2828.79,1950.05) 1(2828.79,1950.05) 1(2865.69,908.74) 1(2865.69,908.74) 1(2865.69,928.42) 1(2865.69,928.42) 1(2865.69,948.7) 1(2865.69,948.7) 1(2865.69,971.73) 1(2865.69,971.73) 1(2865.69,1066.22) 1(2865.69,1066.22) 1(2865.69,1089.25) 1(2865.69,1089.25) 1(2865.69,1109.53) 1(2865.69,1109.53) 1(2865.69,1129.21) 1(2865.69,1129.21) 1(2865.69,1583.74) 1(2865.69,1583.74) 1(2865.69,1603.42) 1(2865.69,1603.42) 1(2865.69,1623.7) 1(2865.69,1623.7) 1(2865.69,1646.73) 1(2865.69,1646.73) 1(2865.69,1741.22) 1(2865.69,1741.22) 1(2865.69,1764.25) 1(2865.69,1764.25) 1(2865.69,1784.53) 1(2865.69,1784.53) 1(2865.69,1804.21) 1(2865.69,1804.21) 1(2877.51,871.34) 1(2877.51,871.34) 1(2877.51,892.99) 1(2877.51,892.99) 1(2877.51,908.74) 1(2877.51,908.74) 1(2877.51,1129.21) 1(2877.51,1129.21) 1(2877.51,1144.96) 1(2877.51,1144.96) 1(2877.51,1166.61) 1(2877.51,1166.61) 1(2877.51,1546.34) 1(2877.51,1546.34) 1(2877.51,1567.99) 1(2877.51,1567.99) 1(2877.51,1583.74) 1(2877.51,1583.74) 1(2877.51,1804.21) 1(2877.51,1804.21) 1(2877.51,1819.96) 1(2877.51,1819.96) 1(2877.51,1841.61) 1(2877.51,1841.61) 1(3062.54,871.34) 1(3062.54,871.34) 1(3062.54,871.34) 1(3062.54,883.15) 1(3062.54,892.99) 1(3062.54,892.99) 1(3062.54,892.99) 1(3062.54,1144.96) 1(3062.54,1144.96) 1(3062.54,1144.96) 1(3062.54,1154.8) 1(3062.54,1166.61) 1(3062.54,1166.61) 1(3062.54,1166.61) 1(3062.54,1546.34) 1(3062.54,1546.34) 1(3062.54,1546.34) 1(3062.54,1558.15) 1(3062.54,1567.99) 1(3062.54,1567.99) 1(3062.54,1567.99) 1(3062.54,1819.96) 1(3062.54,1819.96) 1(3062.54,1819.96) 1(3062.54,1829.8) 1(3062.54,1841.61) 1(3062.54,1841.61) 1(3062.54,1841.61) 1(3062.67,883.15) 1(3062.67,1154.8) 1(3062.67,1558.15) 1(3062.67,1829.8) 1(3062.67,883.15) 1(3062.67,1154.8) 1(3062.67,1558.15) 1(3062.67,1829.8) 1(3065.33,892.99) 1(3065.33,892.99) 1(3065.33,892.99) 1(3065.33,1144.96) 1(3065.33,1144.96) 1(3065.33,1144.96) 1(3065.33,1567.99) 1(3065.33,1567.99) 1(3065.33,1567.99) 1(3065.33,1819.96) 1(3065.33,1819.96) 1(3065.33,1819.96) 1(3065.48,864.75) 1(3065.48,864.75) 1(3065.48,1173.2) 1(3065.48,1173.2) 1(3065.48,1539.75) 1(3065.48,1539.75) 1(3065.48,1848.2) 1(3065.48,1848.2) 1(3065.58,1144.95) 1(3065.58,1144.95) 1(3065.58,1819.95) 1(3065.58,1819.95) 1(3065.68,893.01) 1(3065.68,893.01) 1(3065.68,1568.01) 1(3065.68,1568.01) 1(3065.82,1144.92) 1(3065.82,1144.92) 1(3065.82,1819.92) 1(3065.82,1819.92) 1(3065.92,893.05) 1(3065.92,893.05) 1(3065.92,1568.05) 1(3065.92,1568.05) 1(3066.06,1144.87) 1(3066.06,1144.87) 1(3066.06,1819.87) 1(3066.06,1819.87) 1(3066.17,893.1) 1(3066.17,893.1) 1(3066.17,1568.1) 1(3066.17,1568.1) 1(3066.31,1144.8) 1(3066.31,1144.8) 1(3066.31,1819.8) 1(3066.31,1819.8) 1(3066.41,893.18) 1(3066.41,893.18) 1(3066.41,1568.18) 1(3066.41,1568.18) 1(3066.55,1144.71) 1(3066.55,1144.71) 1(3066.55,1819.71) 1(3066.55,1819.71) 1(3066.64,893.28) 1(3066.64,893.28) 1(3066.64,1568.28) 1(3066.64,1568.28) 1(3066.78,1144.61) 1(3066.78,1144.61) 1(3066.78,1819.61) 1(3066.78,1819.61) 1(3066.88,893.39) 1(3066.88,893.39) 1(3066.88,1568.39) 1(3066.88,1568.39) 1(3067.01,1144.48) 1(3067.01,1144.48) 1(3067.01,1819.48) 1(3067.01,1819.48) 1(3067.11,893.53) 1(3067.11,893.53) 1(3067.11,1568.53) 1(3067.11,1568.53) 1(3067.24,1144.34) 1(3067.24,1144.34) 1(3067.24,1819.34) 1(3067.24,1819.34) 1(3067.34,893.68) 1(3067.34,893.68) 1(3067.34,1568.68) 1(3067.34,1568.68) 1(3067.47,1144.18) 1(3067.47,1144.18) 1(3067.47,1819.18) 1(3067.47,1819.18) 1(3067.56,893.85) 1(3067.56,893.85) 1(3067.56,1568.85) 1(3067.56,1568.85) 1(3067.69,1143.99) 1(3067.69,1143.99) 1(3067.69,1818.99) 1(3067.69,1818.99) 1(3067.77,894.03) 1(3067.77,894.03) 1(3067.77,1569.03) 1(3067.77,1569.03) 1(3067.9,1143.8) 1(3067.9,1143.8) 1(3067.9,1818.8) 1(3067.9,1818.8) 1(3067.98,894.24) 1(3067.98,894.24) 1(3067.98,1569.24) 1(3067.98,1569.24) 1(3068.1,1143.58) 1(3068.1,1143.58) 1(3068.1,1818.58) 1(3068.1,1818.58) 1(3068.19,894.46) 1(3068.19,894.46) 1(3068.19,1569.46) 1(3068.19,1569.46) 1(3068.3,1143.35) 1(3068.3,1143.35) 1(3068.3,1818.35) 1(3068.3,1818.35) 1(3068.38,894.7) 1(3068.38,894.7) 1(3068.38,1569.7) 1(3068.38,1569.7) 1(3068.49,1143.11) 1(3068.49,1143.11) 1(3068.49,1818.11) 1(3068.49,1818.11) 1(3068.57,894.95) 1(3068.57,894.95) 1(3068.57,1569.95) 1(3068.57,1569.95) 1(3068.68,1142.85) 1(3068.68,1142.85) 1(3068.68,1817.85) 1(3068.68,1817.85) 1(3068.69,857.56) 1(3068.69,857.56) 1(3068.69,1180.39) 1(3068.69,1180.39) 1(3068.69,1532.56) 1(3068.69,1532.56) 1(3068.69,1855.39) 1(3068.69,1855.39) 1(3068.75,895.22) 1(3068.75,895.22) 1(3068.75,1570.22) 1(3068.75,1570.22) 1(3068.85,1142.57) 1(3068.85,1142.57) 1(3068.85,1817.57) 1(3068.85,1817.57) 1(3068.92,895.5) 1(3068.92,895.5) 1(3068.92,1570.5) 1(3068.92,1570.5) 1(3069.02,1142.28) 1(3069.02,1142.28) 1(3069.02,1817.28) 1(3069.02,1817.28) 1(3069.09,895.79) 1(3069.09,895.79) 1(3069.09,1570.79) 1(3069.09,1570.79) 1(3069.18,1141.98) 1(3069.18,1141.98) 1(3069.18,1816.98) 1(3069.18,1816.98) 1(3069.24,896.1) 1(3069.24,896.1) 1(3069.24,1571.1) 1(3069.24,1571.1) 1(3069.33,1141.67) 1(3069.33,1141.67) 1(3069.33,1816.67) 1(3069.33,1816.67) 1(3069.38,896.42) 1(3069.38,896.42) 1(3069.38,1571.42) 1(3069.38,1571.42) 1(3069.46,1141.34) 1(3069.46,1141.34) 1(3069.46,1816.34) 1(3069.46,1816.34) 1(3069.52,896.75) 1(3069.52,896.75) 1(3069.52,1571.75) 1(3069.52,1571.75) 1(3069.59,1141) 1(3069.59,1141) 1(3069.59,1816) 1(3069.59,1816) 1(3069.64,897.09) 1(3069.64,897.09) 1(3069.64,1572.09) 1(3069.64,1572.09) 1(3069.71,1140.66) 1(3069.71,1140.66) 1(3069.71,1815.66) 1(3069.71,1815.66) 1(3069.75,897.44) 1(3069.75,897.44) 1(3069.75,1572.44) 1(3069.75,1572.44) 1(3069.81,1140.3) 1(3069.81,1140.3) 1(3069.81,1815.3) 1(3069.81,1815.3) 1(3069.85,897.8) 1(3069.85,897.8) 1(3069.85,1572.8) 1(3069.85,1572.8) 1(3069.91,1139.94) 1(3069.91,1139.94) 1(3069.91,1814.94) 1(3069.91,1814.94) 1(3069.94,898.16) 1(3069.94,898.16) 1(3069.94,1573.16) 1(3069.94,1573.16) 1(3069.99,1139.57) 1(3069.99,1139.57) 1(3069.99,1814.57) 1(3069.99,1814.57) 1(3070.02,898.54) 1(3070.02,898.54) 1(3070.02,1573.54) 1(3070.02,1573.54) 1(3070.06,1139.19) 1(3070.06,1139.19) 1(3070.06,1814.19) 1(3070.06,1814.19) 1(3070.09,898.92) 1(3070.09,898.92) 1(3070.09,1573.92) 1(3070.09,1573.92) 1(3070.12,1138.81) 1(3070.12,1138.81) 1(3070.12,1813.81) 1(3070.12,1813.81) 1(3070.14,899.3) 1(3070.14,899.3) 1(3070.14,1574.3) 1(3070.14,1574.3) 1(3070.17,1138.42) 1(3070.17,1138.42) 1(3070.17,1813.42) 1(3070.17,1813.42) 1(3070.19,899.69) 1(3070.19,899.69) 1(3070.19,1574.69) 1(3070.19,1574.69) 1(3070.21,1138.03) 1(3070.21,1138.03) 1(3070.21,1813.03) 1(3070.21,1813.03) 1(3070.22,900.08) 1(3070.22,900.08) 1(3070.22,1575.08) 1(3070.22,1575.08) 1(3070.23,1137.64) 1(3070.23,1137.64) 1(3070.23,1812.64) 1(3070.23,1812.64) 1(3070.24,900.47) 1(3070.24,900.47) 1(3070.24,1575.47) 1(3070.24,1575.47) 1(3070.24,900.86) 1(3070.24,900.86) 1(3070.24,1137.08) 1(3070.24,1137.08) 1(3070.24,1575.86) 1(3070.24,1575.86) 1(3070.24,1812.08) 1(3070.24,1812.08) 1(3073.28,876.26) 1(3073.28,1161.69) 1(3073.28,1551.26) 1(3073.28,1836.69) 1(3073.28,876.26) 1(3073.28,1161.69) 1(3073.28,1551.26) 1(3073.28,1836.69) 1(3074.56,892.99) 1(3074.56,892.99) 1(3074.56,1144.96) 1(3074.56,1144.96) 1(3074.56,1567.99) 1(3074.56,1567.99) 1(3074.56,1819.96) 1(3074.56,1819.96) 1(3074.81,1144.95) 1(3074.81,1144.95) 1(3074.81,1819.95) 1(3074.81,1819.95) 1(3074.91,893.01) 1(3074.91,893.01) 1(3074.91,1568.01) 1(3074.91,1568.01) 1(3075.05,1144.92) 1(3075.05,1144.92) 1(3075.05,1819.92) 1(3075.05,1819.92) 1(3075.15,893.05) 1(3075.15,893.05) 1(3075.15,1568.05) 1(3075.15,1568.05) 1(3075.3,1144.87) 1(3075.3,1144.87) 1(3075.3,1819.87) 1(3075.3,1819.87) 1(3075.4,893.1) 1(3075.4,893.1) 1(3075.4,1568.1) 1(3075.4,1568.1) 1(3075.54,1144.8) 1(3075.54,1144.8) 1(3075.54,1819.8) 1(3075.54,1819.8) 1(3075.64,893.18) 1(3075.64,893.18) 1(3075.64,1568.18) 1(3075.64,1568.18) 1(3075.78,1144.71) 1(3075.78,1144.71) 1(3075.78,1819.71) 1(3075.78,1819.71) 1(3075.88,893.28) 1(3075.88,893.28) 1(3075.88,1568.28) 1(3075.88,1568.28) 1(3076.01,1144.61) 1(3076.01,1144.61) 1(3076.01,1819.61) 1(3076.01,1819.61) 1(3076.11,893.39) 1(3076.11,893.39) 1(3076.11,1568.39) 1(3076.11,1568.39) 1(3076.25,1144.48) 1(3076.25,1144.48) 1(3076.25,1819.48) 1(3076.25,1819.48) 1(3076.27,869.56) 1(3076.27,869.56) 1(3076.27,1168.39) 1(3076.27,1168.39) 1(3076.27,1544.56) 1(3076.27,1544.56) 1(3076.27,1843.39) 1(3076.27,1843.39) 1(3076.34,893.53) 1(3076.34,893.53) 1(3076.34,1568.53) 1(3076.34,1568.53) 1(3076.48,1144.34) 1(3076.48,1144.34) 1(3076.48,1819.34) 1(3076.48,1819.34) 1(3076.57,893.68) 1(3076.57,893.68) 1(3076.57,1568.68) 1(3076.57,1568.68) 1(3076.7,1144.18) 1(3076.7,1144.18) 1(3076.7,1819.18) 1(3076.7,1819.18) 1(3076.79,893.85) 1(3076.79,893.85) 1(3076.79,1568.85) 1(3076.79,1568.85) 1(3076.92,1143.99) 1(3076.92,1143.99) 1(3076.92,1818.99) 1(3076.92,1818.99) 1(3077.01,894.03) 1(3077.01,894.03) 1(3077.01,1569.03) 1(3077.01,1569.03) 1(3077.13,1143.8) 1(3077.13,1143.8) 1(3077.13,1818.8) 1(3077.13,1818.8) 1(3077.22,894.24) 1(3077.22,894.24) 1(3077.22,1569.24) 1(3077.22,1569.24) 1(3077.34,1143.58) 1(3077.34,1143.58) 1(3077.34,1818.58) 1(3077.34,1818.58) 1(3077.42,894.46) 1(3077.42,894.46) 1(3077.42,1569.46) 1(3077.42,1569.46) 1(3077.53,1143.35) 1(3077.53,1143.35) 1(3077.53,1818.35) 1(3077.53,1818.35) 1(3077.62,894.7) 1(3077.62,894.7) 1(3077.62,1569.7) 1(3077.62,1569.7) 1(3077.73,1143.11) 1(3077.73,1143.11) 1(3077.73,1818.11) 1(3077.73,1818.11) 1(3077.8,894.95) 1(3077.8,894.95) 1(3077.8,1569.95) 1(3077.8,1569.95) 1(3077.91,1142.85) 1(3077.91,1142.85) 1(3077.91,1817.85) 1(3077.91,1817.85) 1(3077.98,895.22) 1(3077.98,895.22) 1(3077.98,1570.22) 1(3077.98,1570.22) 1(3078.09,1142.57) 1(3078.09,1142.57) 1(3078.09,1817.57) 1(3078.09,1817.57) 1(3078.16,895.5) 1(3078.16,895.5) 1(3078.16,1570.5) 1(3078.16,1570.5) 1(3078.25,1142.28) 1(3078.25,1142.28) 1(3078.25,1817.28) 1(3078.25,1817.28) 1(3078.32,895.79) 1(3078.32,895.79) 1(3078.32,1570.79) 1(3078.32,1570.79) 1(3078.41,1141.98) 1(3078.41,1141.98) 1(3078.41,1816.98) 1(3078.41,1816.98) 1(3078.47,896.1) 1(3078.47,896.1) 1(3078.47,1571.1) 1(3078.47,1571.1) 1(3078.56,1141.67) 1(3078.56,1141.67) 1(3078.56,1816.67) 1(3078.56,1816.67) 1(3078.62,896.42) 1(3078.62,896.42) 1(3078.62,1571.42) 1(3078.62,1571.42) 1(3078.7,1141.34) 1(3078.7,1141.34) 1(3078.7,1816.34) 1(3078.7,1816.34) 1(3078.75,896.75) 1(3078.75,896.75) 1(3078.75,1571.75) 1(3078.75,1571.75) 1(3078.82,1141) 1(3078.82,1141) 1(3078.82,1816) 1(3078.82,1816) 1(3078.87,897.09) 1(3078.87,897.09) 1(3078.87,1572.09) 1(3078.87,1572.09) 1(3078.94,1140.66) 1(3078.94,1140.66) 1(3078.94,1815.66) 1(3078.94,1815.66) 1(3078.98,897.44) 1(3078.98,897.44) 1(3078.98,1572.44) 1(3078.98,1572.44) 1(3079.05,1140.3) 1(3079.05,1140.3) 1(3079.05,1815.3) 1(3079.05,1815.3) 1(3079.09,897.8) 1(3079.09,897.8) 1(3079.09,1572.8) 1(3079.09,1572.8) 1(3079.14,1139.94) 1(3079.14,1139.94) 1(3079.14,1814.94) 1(3079.14,1814.94) 1(3079.18,898.16) 1(3079.18,898.16) 1(3079.18,1573.16) 1(3079.18,1573.16) 1(3079.22,1139.57) 1(3079.22,1139.57) 1(3079.22,1814.57) 1(3079.22,1814.57) 1(3079.25,898.54) 1(3079.25,898.54) 1(3079.25,1573.54) 1(3079.25,1573.54) 1(3079.29,1139.19) 1(3079.29,1139.19) 1(3079.29,1814.19) 1(3079.29,1814.19) 1(3079.32,898.92) 1(3079.32,898.92) 1(3079.32,1573.92) 1(3079.32,1573.92) 1(3079.35,1138.81) 1(3079.35,1138.81) 1(3079.35,1813.81) 1(3079.35,1813.81) 1(3079.38,899.3) 1(3079.38,899.3) 1(3079.38,1574.3) 1(3079.38,1574.3) 1(3079.4,1138.42) 1(3079.4,1138.42) 1(3079.4,1813.42) 1(3079.4,1813.42) 1(3079.42,899.69) 1(3079.42,899.69) 1(3079.42,1574.69) 1(3079.42,1574.69) 1(3079.44,1138.03) 1(3079.44,1138.03) 1(3079.44,1813.03) 1(3079.44,1813.03) 1(3079.45,900.08) 1(3079.45,900.08) 1(3079.45,1575.08) 1(3079.45,1575.08) 1(3079.46,1137.64) 1(3079.46,1137.64) 1(3079.46,1812.64) 1(3079.46,1812.64) 1(3079.47,900.47) 1(3079.47,900.47) 1(3079.47,1575.47) 1(3079.47,1575.47) 1(3079.47,862.37) 1(3079.47,862.37) 1(3079.47,900.86) 1(3079.47,900.86) 1(3079.47,1137.08) 1(3079.47,1137.08) 1(3079.47,1175.58) 1(3079.47,1175.58) 1(3079.47,1537.37) 1(3079.47,1537.37) 1(3079.47,1575.86) 1(3079.47,1575.86) 1(3079.47,1812.08) 1(3079.47,1812.08) 1(3079.47,1850.58) 1(3079.47,1850.58)
  round 61.02 on Mech16: 1(1092.42,-1350) 1(1092.42,-1250) 1(1158.79,-756.95) 1(1158.79,-656.95) 1(1269.42,459) 1(1269.42,559) 1(2148.79,1328.05) 1(2148.79,1428.05) 1(2661.79,613.05) 1(2661.79,713.05)
  round 140 on Mech16: 1(1107.43,2610.14)
  round 9.84 on Mech16: 1(1397.29,738.51) 1(1407.13,738.51) 1(1856.47,471.4) 1(1864.97,471.4) 1(1947.13,311.32) 1(1947.13,331.01) 1(1947.13,390.06) 1(1947.13,350.69) 1(1947.13,370.38) 1(1982.57,311.32) 1(1982.57,331.01) 1(1982.57,390.06) 1(1982.57,350.69) 1(1982.57,370.38) 1(2005.44,-824.9) 1(2005.44,-805.22) 1(2005.44,-746.16) 1(2005.44,-785.53) 1(2005.44,-765.85) 1(2040.87,-824.9) 1(2040.87,-805.22) 1(2040.87,-746.16) 1(2040.87,-785.53) 1(2040.87,-765.85) 1(2114.46,350.69) 1(2114.46,370.38) 1(2114.46,311.32) 1(2114.46,331.01) 1(2114.46,390.06) 1(2149.89,350.69) 1(2149.89,370.38) 1(2149.89,311.32) 1(2149.89,331.01) 1(2149.89,390.06) 1(2172.76,-785.53) 1(2172.76,-765.85) 1(2172.76,-824.9) 1(2172.76,-805.22) 1(2172.76,-746.16) 1(2208.19,-785.53) 1(2208.19,-765.85) 1(2208.19,-824.9) 1(2208.19,-805.22) 1(2208.19,-746.16) 1(2465.41,-608.32) 1(2465.41,-588.63) 1(2465.41,-568.95) 1(2465.41,-549.26) 1(2465.41,-529.58) 1(2500.84,-608.32) 1(2500.84,-588.63) 1(2500.84,-568.95) 1(2500.84,-549.26) 1(2500.84,-529.58) 1(2632.73,-608.32) 1(2632.73,-588.63) 1(2632.73,-568.95) 1(2632.73,-549.26) 1(2632.73,-529.58) 1(2668.16,-608.32) 1(2668.16,-588.63) 1(2668.16,-568.95) 1(2668.16,-549.26) 1(2668.16,-529.58) 1(2708.62,1005.28) 1(2742.13,1650.2)
  round 19.69 on Mech16: 1(1402.21,738.51)
  round 27.56 on Mech16: 1(1440.59,768.82)
  round 23.62 on Mech16: 1(1460.28,800.32) 1(1483.9,800.32) 1(2080.01,-301.77)
  round 47.24 on Mech16: 1(1472.09,800.32) 1(2964.62,880.6) 1(2964.62,1156.19) 1(2964.62,1555.6) 1(2964.62,1831.19) 1(2992.18,880.6) 1(2992.18,1156.19) 1(2992.18,1555.6) 1(2992.18,1831.19)
  round 125.2 on Mech16: 1(1505.8,-2011) 1(2005.8,-2011)
  round 8 on Mech16: 1(1661.42,302.71) 1(1661.42,333.05) 1(1817.14,59.25) 1(1817.14,59.25) 1(1824.58,-0.61) 1(1824.58,66.7) 1(1824.58,66.7) 1(1826.22,66.7) 1(1833.66,59.25) 1(1833.66,59.25)
  round 6.89 on Mech16: 1(1880.84,466.58) 1(1880.84,473.47) 1(1880.84,492.17) 1(1880.84,499.06) 1(1880.84,517.76) 1(1880.84,524.65) 1(1880.84,543.35) 1(1880.84,550.24) 1(1940.88,466.58) 1(1940.88,473.47) 1(1940.88,492.17) 1(1940.88,499.06) 1(1940.88,517.76) 1(1940.88,524.65) 1(1940.88,543.35) 1(1940.88,550.24) 1(2105.25,466.58) 1(2105.25,473.47) 1(2105.25,492.17) 1(2105.25,499.06) 1(2105.25,517.76) 1(2105.25,524.65) 1(2105.25,543.35) 1(2105.25,550.24) 1(2165.29,466.58) 1(2165.29,473.47) 1(2165.29,492.17) 1(2165.29,499.06) 1(2165.29,517.76) 1(2165.29,524.65) 1(2165.29,543.35) 1(2165.29,550.24)
  round 6.69 on Mech16: 1(1946.82,-547.35) 1(1946.82,-523.73) 1(1953.05,60.65) 1(1953.05,84.27) 1(2041.31,-547.35) 1(2041.31,-523.73) 1(2047.54,60.65) 1(2047.54,84.27) 1(2052.75,-624.34) 1(2052.75,-553.47) 1(2055.93,90.66) 1(2055.93,161.53) 1(2131.49,-624.34) 1(2131.49,-553.47) 1(2134.67,90.66) 1(2134.67,161.53) 1(2144.75,-622.34) 1(2144.75,-551.47) 1(2144.93,89.66) 1(2144.93,160.53) 1(2223.49,-622.34) 1(2223.49,-551.47) 1(2223.67,89.66) 1(2223.67,160.53) 1(2235.39,60.65) 1(2235.39,84.27) 1(2236.39,-547.35) 1(2236.39,-523.73) 1(2329.88,60.65) 1(2329.88,84.27) 1(2330.88,-547.35) 1(2330.88,-523.73)
  round 2.76 on Mech16: 1(1950.76,-588.69) 1(1950.76,-588.69) 1(1950.76,-482.39) 1(1950.76,-482.39) 1(1956.99,19.31) 1(1956.99,19.31) 1(1956.99,125.61) 1(1956.99,125.61) 1(2037.38,-588.69) 1(2037.38,-588.69) 1(2037.38,-482.39) 1(2037.38,-482.39) 1(2043.6,19.31) 1(2043.6,19.31) 1(2043.6,125.61) 1(2043.6,125.61) 1(2054.71,-657.8) 1(2054.71,-657.8) 1(2054.71,-520.01) 1(2054.71,-520.01) 1(2057.9,57.2) 1(2057.9,57.2) 1(2057.9,194.99) 1(2057.9,194.99) 1(2129.52,-657.8) 1(2129.52,-657.8) 1(2129.52,-520.01) 1(2129.52,-520.01) 1(2132.7,57.2) 1(2132.7,57.2) 1(2132.7,194.99) 1(2132.7,194.99) 1(2146.71,-655.8) 1(2146.71,-655.8) 1(2146.71,-518.01) 1(2146.71,-518.01) 1(2146.9,56.2) 1(2146.9,56.2) 1(2146.9,193.99) 1(2146.9,193.99) 1(2221.52,-655.8) 1(2221.52,-655.8) 1(2221.52,-518.01) 1(2221.52,-518.01) 1(2221.7,56.2) 1(2221.7,56.2) 1(2221.7,193.99) 1(2221.7,193.99) 1(2239.33,19.31) 1(2239.33,19.31) 1(2239.33,125.61) 1(2239.33,125.61) 1(2240.33,-588.69) 1(2240.33,-588.69) 1(2240.33,-482.39) 1(2240.33,-482.39) 1(2325.94,19.31) 1(2325.94,19.31) 1(2325.94,125.61) 1(2325.94,125.61) 1(2326.94,-588.69) 1(2326.94,-588.69) 1(2326.94,-482.39) 1(2326.94,-482.39)
  round 21.42 on Mech16: 1(2060.62,976.3)
  round 3.15 on Mech16: 1(2075.46,856.82) 1(2075.46,856.82) 1(2075.46,959.18) 1(2075.46,959.18) 1(2089.24,939.49) 1(2104.98,939.49) 1(2205.38,856.82) 1(2205.38,856.82) 1(2205.38,959.18) 1(2205.38,959.18)
  round 18.9 on Mech16: 1(2097.11,939.49)
  round 74 on Mech16: 1(2486.92,-100.07)
  round 26.34 on Mech16: 1(2517.17,314.72)
  round 80 on Mech16: 1(2534.79,-1472.95)
  round 69.78 on Mech16: 1(2608.32,-881.47)
  round 22.01 on Mech16: 1(2701.26,961)
  round 1.97 on Mech16: 1(2704.68,1005.28) 1(2712.56,1005.28) 1(2738.2,1650.2) 1(2746.07,1650.2)
  round 29.53 on Mech16: 1(2723.39,-1890.57) 1(2723.39,-1713.4) 1(2752.92,-1890.57) 1(2752.92,-1713.4)
  round 59.06 on Mech16: 1(2797.21,-1616.95) 1(2915.32,-1616.95) 1(2974.38,-1861.04) 1(2974.38,-1742.93)
  round 20.19 on Mech16: 1(2844.89,1070.45) 1(2844.89,1745.45)
  round 33.46 on Mech16: 1(2857.68,-1370.53) 1(2857.68,-1337.07) 1(2857.68,-925.53) 1(2857.68,-892.07) 1(2891.15,-1370.53) 1(2891.15,-1337.07) 1(2891.15,-925.53) 1(2891.15,-892.07)
  round 66.93 on Mech16: 1(2874.42,-1216) 1(2874.42,-1078.21) 1(2874.42,-771) 1(2874.42,-633.21)
  round 30.12 on Mech16: 1(2921.36,64.94) 1(2921.36,95.06) 1(2951.48,64.94) 1(2951.48,95.06)
  round 157.48 hole 118.11: TH1(1017.68,3562.29) TH2(91.81,124.38) TH2(1017.68,1322.29) TH2(2662.29,124.38) TH2(3991.74,1322.29) TH9(3991.74,3562.29) TH10(91.81,3600.41)
  round 160 hole 160 unplated: ""(150,-204.34) ""(150,3929.13) ""(3944.49,-204.34) ""(3944.49,3929.13)

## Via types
v1: diameter 13.77, hole 7, Top Layer to L2_GND1, tented top, 4306 vias
v2: diameter 18, hole 8, Top Layer to Bottom Layer, tented both sides, 946 vias
v3: diameter 19.68, hole 8, Top Layer to Bottom Layer, tented both sides, 6 vias

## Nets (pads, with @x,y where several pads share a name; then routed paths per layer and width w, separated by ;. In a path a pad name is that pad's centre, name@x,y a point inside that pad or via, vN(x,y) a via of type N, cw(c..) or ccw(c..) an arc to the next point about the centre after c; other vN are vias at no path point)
3V3_LDO_EN: R11.2 R241.2 U13.4 | length 84.5
  Top Layer w10.8: U13.4@3221.04,420.15 R241.2@3251.04,420.15 R11.2@3305.55,420.15
5V_IN_USB: C42.2 C46.2 C47.1 C55.1 C66.1 C67.2 C84.1 C85.2 D1.1 D12.1 R1.2 R27.1 R35.2 R36.2 R69.2 TP14.1 U13.6 U14.2 | length 5099.5
  Top Layer w15: R69.2@690.72,2121.22 R69.2@690.72,2122.21
  Top Layer w20: R69.2@690.72,2122.21 v2@690.72,2150.72 ; R27.1@3042.78,641.13 3042.78,605.09 3089.48,558.39 3202.24,558.39 ; C42.2@3219.71,508.22 3224.78,513.29 3224.78,535.84 3202.24,558.39 ; 3236.26,570.15 3224.5,558.39 3202.24,558.39 ; v2(3245.56,910.91) 3308.96,910.91 3317.23,902.64 R36.2@3317.23,871.48
  L5_PWR2 w30: v2(690.46,2150.97) 548.96,2009.48 548.96,1876.46 492.18,1819.68 492.18,1107.82 1100.23,499.77 1608.35,499.77 1650.98,457.13 2798.87,457.13 2891.65,364.35 3488.06,364.35 v2(3602.59,478.88)
  Bottom Layer w15: R35.2@3189.08,914.94 3193.11,910.91 v2@3244.75,910.91
  other v2: 3616.59,456.69 3649.07,457.22 3685.25,456.69 3632.43,478.88 3665.71,478.88 3608.37,1287.47 3630.56,1301.46 3608.37,1317.31 3630.03,1333.95 3608.37,1350.58 3630.56,1369.48
5V_OVP2: R35.1 R74.2 U14.4 | length 129
  Top Layer w7: U14.4@3159.04,800.34 3159.04,819.23 3166,826.19 v2(3166,828.53)
  Top Layer w10.8: v2(3166,828.53) 3177.84,840.37 3179.2,840.37 3189.26,850.43 R74.2@3189.26,867.3
  Bottom Layer w8.7: v2(3166,828.53) 3176.57,839.1 3176.57,851.26 3189.08,863.76 R35.1@3189.08,867.7
12V_DC_JACK: C48.1 C63.1 D2.2 J7.1 U10.4 U10.5 U10.6
12V_OVP1: R4.1 R20.2 U14.5 | length 107.9
  Top Layer w7: U14.5@3139.35,800.34 v2@3139.35,826.46
  Top Layer w10.8: v2(3139.19,826.62) 3139.35,826.46 3139.35,867.06 R4.1@3139.58,867.3
  Bottom Layer w8.7: v2(3139.19,826.62) 3139.44,826.87 R20.2@3139.44,867.18
CAN1_STB: R131.2 R133.2 R144.2 U19.8 | length 130
  Top Layer w10.8: U19.8@354.01,1570.14 R144.2@354.01,1510.14 R131.2@384.01,1510.14 R133.2@384.01,1470.14
CAN_FD_B_H: J8.3 R130.2 U19.7 | length 283.1
  Top Layer w4.3: J8.3@158.07,1539.71 163.08,1544.71 163.08,1583.65 215.71,1636.29 260.31,1636.29 266.32,1630.27 266.32,1629.8 273.54,1622.58 274.01,1622.58 R130.2@274.01,1620.14 ; R130.2@274.01,1622.93 274.83,1622.93 281.71,1629.8 281.71,1630.62 291.33,1640.24 305.21,1640.24 325.31,1620.14 U19.7@354.01,1620.14
CAN_FD_B_L: J8.1 R140.1 U19.6 | length 281.8
  Top Layer w4.3: J8.1@158.07,1739.71 158.07,1705.6 217.58,1646.09 252.12,1646.09 266.32,1660.29 266.32,1660.48 R140.1@274.01,1668.17 ; R140.1@274.01,1670.14 R140.1@274.01,1668.17 ; U19.6@354.01,1670.14 324.77,1670.14 304.67,1650.04 292.15,1650.04 281.71,1660.48 R140.1@274.01,1668.17
CAN_FD_B_PHY_RX: R143.1 U1.AA16 | length 2305.1
  Top Layer w4: 1992.88,2647.8 2014.61,2647.8 2021.63,2654.82 U1.AA16@2073.47,2654.82
  Top Layer w10.8: v2(545.18,1810.75) R143.1@570.3,1810.75 ; v2(1952,2628.63) 1971.16,2647.8 1992.88,2647.8
  L3_SIG1 w6: v2(545.18,1810.75) 596.55,1862.11 596.55,2141.56 611.54,2156.56 611.54,2325.3 v2(597.33,2339.51)
  L6_SIG2 w6: v2(597.33,2339.51) 645.44,2387.62 1029.3,2387.62 1077.45,2339.47 1201.86,2339.47 1226.98,2364.6 1809.6,2364.6 1952,2507 v2(1952,2628.63)
CAN_FD_B_PHY_TX: R132.1 U1.AA14 | length 2510.7
  Top Layer w8: v2(2015.2,2713.42) 2046.12,2713.42 2065.35,2694.19 U1.AA14@2073.47,2694.19
  Top Layer w10.8: v2(526.37,1543.25) 526.99,1542.64 R132.1@526.99,1517.78
  L3_SIG1 w6: v2(526.37,1543.25) 526.37,1826.18 567.88,1867.69 567.88,2158.16 v2(567.54,2158.5)
  L6_SIG2 w6: v2(567.54,2158.5) 599.21,2190.17 1082.52,2190.17 1241.97,2349.61 1818.77,2349.61 1973.73,2504.58 1973.73,2690.13 1997.02,2713.42 v2(2015.2,2713.42)
CAN_FD_B_STB_CTRL: R133.1 S1.1 | length 2831
  Top Layer w10.8: R133.1@424.37,1470.14 450.83,1470.14 457.54,1463.43 v2(459.49,1463.43) ; S1.1@546.89,3639.18 546.89,3557.53 v2@615.88,3488.54
  L3_SIG1 w6: v2(459.49,1463.43) 413.01,1509.91 413.01,1897.26 476.61,1960.86 476.61,2015.13 403.18,2088.56 403.18,2666.57 476.55,2739.94 476.55,3056.45 245.08,3287.92 245.08,3465.55 303.15,3523.62 581.13,3523.62 v2(616.05,3488.71)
